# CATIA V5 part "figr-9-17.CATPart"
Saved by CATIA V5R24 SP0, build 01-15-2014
Part number: Part1
Bounding box of the stored display mesh (mm): x -77.304 to 77.304, y -77.304 to 125.507, z 0 to 125
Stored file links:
  D:\KAVITA\CATIA V5-6R2014 Project_ Kavita\CATIA V5-6R2014_partfiles\Partfiles\c09_catia_v5-6r2014_prt\figr-9-17.CATPart
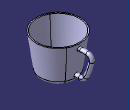
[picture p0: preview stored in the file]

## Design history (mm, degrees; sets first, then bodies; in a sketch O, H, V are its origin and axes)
Set1
  Plane1: type Normal, Curve Sketch3, RefPoint vertex of Sketch3
Body1 (main body)
  Sketch1 on yz-plane, origin (0, 0, 0), H (0, 1, 0), V (0, 0, 1)
    line L1 (0, 0) -> (60, 0)
    point P1 (60, 0)
    point P2 (60, 0)
    line L2 (60, 0) -> (77.5, 125)
    point P3 (77.5, 125)
    line L3 (77.5, 125) -> (0, 125)
    point P4 (0, 125)
    line L4 (0, 125) -> (0, 0)
    axis line L5 (0, 150.2858) -> (0, -31.0593)
    point P5 (0, 150.2858)
    radius about axis P1 L5 = 60
    radius about axis P3 L5 = 77.5
    distance L3 L1 = 125
    horizontal: L1 H, L3 H
    coincidence: P4 V, P2 P1, P5 V
    vertical: L4 V, L5 V
  Shaft1: profile Sketch1, axis Sketch1.L5, angle 360
  Fillet1: radius 15, on edge [face of Shaft1 | face of Shaft1]
  Shell1: ExtOffset 0, Face face of Shaft1, IntOffset 4
  Sketch2 on Plane1, origin (0, 62.9841, 0), H (-1, 0, 0), V (0, 0, 1)
    circle A1 centre (0, 22.002) radius 7.5
    reference projected point E1 (0, 22.002) from vertex of Sketch3
    radius A1 = 7.5
    concentricity: A1 E1
  Sketch3 on yz-plane, origin (0, 0, 0), H (0, 1, 0), V (0, 0, 1)
    line L1 (62.9841, 22.002) -> (78.2172, 22.002)
    arc A1 centre (78.2172, 44.1133) radius 22.1113 from (78.2172, 22.002) to (97.9307, 34.0988) ccw
    arc A2 centre (-112.3295, 140.9107) radius 235.8349 from (97.9307, 34.0988) to (117.8681, 89.6549) ccw
    arc A3 centre (104.0328, 92.7355) radius 14.1742 from (117.8681, 89.6549) to (104.4272, 106.9041) ccw
    arc A4 centre (93.6744, -279.4123) radius 386.4661 from (104.4272, 106.9041) to (82.9216, 106.9041) ccw
    horizontal: L1 H
    tangency: A1 L1, A2 A1, A3 A2, A4 A3
  Rib1: profile Sketch2, centre curve Sketch3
